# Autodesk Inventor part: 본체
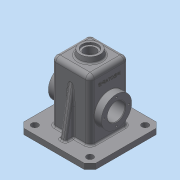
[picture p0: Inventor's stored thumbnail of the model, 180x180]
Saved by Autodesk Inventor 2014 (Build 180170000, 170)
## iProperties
Created: 2016-02
Part Number: 본체
Material: 일반
Document SubType Name: Modeling
Designer: 406-강의용
Density: 1 g/cm^3
Appearance: 기본값
Author: 406-강의용
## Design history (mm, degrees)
sketch "스케치1"
  geometry: L1 (-65, 0)-(65, 0); L2 (65, 0)-(65, 10); L3 (65, 10)-(-65, 10); L4 (-65, 10)-(-65, 0); 2 further points
  constraints: 8 end point, 2 parallel, 1 coincident, 1 horizontal, 1 midpoint, 1 perpendicular
  dimensions: "d0" = 130 distance between parallel lines of L4 L2; "d1" = 10 distance between parallel lines of L1 L3
extrude "돌출1" new body sketch "스케치1" distance "d2" = 130; taper "d3" = 0 deg
sketch "스케치2"
  geometry: L1 (130, 0)-(0, 0) reference; L2 (130, 0)-(130, -130) reference; L3 (30, -100)-(100, -100); L4 (100, -100)-(100, -30); L5 (100, -30)-(30, -30); L6 (30, -30)-(30, -100); 5 further points
  constraints: 8 end point, 4 midpoint, 2 parallel, 1 horizontal, 1 horizontal alignment, 1 perpendicular, 1 vertical alignment
  dimensions: "d4" = 70 distance between parallel lines of L3 L5; "d5" = 70 distance between parallel lines of L6 L4
extrude "돌출2" join sketch "스케치2" distance "d6" = 110; taper "d7" = 0 deg
sketch "스케치3"
  geometry: L1 (35, 35)-(95, 35); L2 (95, 35)-(95, 95); L3 (95, 95)-(35, 95); L4 (35, 95)-(35, 35); L5 (100, 100)-(30, 100) reference; L6 (100, 30)-(100, 100) reference; L7 (30, 30)-(100, 30) reference; 1 further point
  constraints: 8 end point, 2 parallel, 2 perpendicular, 1 horizontal
  dimensions: "d8" = 5 distance between parallel lines of L5 L3; "d9" = 5 distance between parallel lines of L6 L2; "d10" = 5 distance between parallel lines of L7 L1
extrude "돌출3" cut sketch "스케치3" distance "d11" = 115; taper "d12" = 0 deg
fillet "모깎기1" dims "d13" = 8
fillet "모깎기2" dims "d14" = 8
chamfer "모따기1" distance "d15" = 10; stored, may be unused: second distance "d16" = 2, angle "d17" = 45 deg
node "작업 평면1"
sketch "스케치4"
  geometry: L1 (90, 112)-(90, 10) reference; L2 (90, 10)-(120, 10) reference; L3 (120, 10)-(120, 0) reference; L4 (120, 0)-(85, 0) reference; L5 (85, 0)-(85, 115) reference; L6 (85, 115)-(25, 115) reference; L7 (25, 115)-(25, 0) reference; L8 (25, 0)-(-10, 0) reference; L9 (-10, 0)-(-10, 10) reference; L10 (-10, 10)-(20, 10) reference; L11 (20, 10)-(20, 112) reference; L12 (28, 120)-(82, 120) reference; L13 (105, 10)-(90, 95.069); A1 r 8 centre (82, 112) between (90, 112) and (82, 120) reference; A2 r 8 centre (28, 112) between (28, 120) and (20, 112) reference
  constraints: 2 end point, 1 midpoint, 1 point on line
  dimensions: "d18" = 100 deg angle of L2 L13; "d19" = 15 distance from line of L3 L13.start
extrude "돌출4" join sketch "스케치4" stored distance "d20" = 10; taper "d21" = 0 deg
fillet "모깎기3" dims "d22" = 3
fillet "모깎기4" dims "d23" = 3
node "작업 평면2"
fillet "모깎기5" dims "d24" = 3
node "작업 평면3"
sketch "스케치6"
  geometry: L1 (62, 0)-(62, -99) reference; L2 (65, -102)-(92, -102) reference; L3 (92, -102)-(92, -112) reference; L4 (92, -112)-(57, -112) reference; L5 (57, -112)-(57, 3) reference; L6 (57, 3)-(-3, 3) reference; L7 (-3, 3)-(-3, -112) reference; L8 (-3, -112)-(-38, -112) reference; L9 (-38, -112)-(-38, -102) reference; L10 (-38, -102)-(-11, -102) reference; L11 (-8, -99)-(-8, 0) reference; L12 (0, 8)-(54, 8) reference; L13 (50, -57)-(75, -57); L14 (50, -41)-(75, -41); L15 (75, -41)-(75, -29.5); L16 (75, -29.5)-(57, -29.5); L17 (57, -29.5)-(50, -36.5); L18 (50, -36.5)-(50, -41); A1 r 8 centre (54, 0) between (62, 0) and (54, 8) reference; A2 r 3 centre (65, -99) between (62, -99) and (65, -102) reference; A3 r 3 centre (-11, -99) between (-11, -102) and (-8, -99) reference; A4 r 8 centre (0, 0) between (0, 8) and (-8, 0) reference; 1 further point
  constraints: 12 end point, 3 perpendicular, 2 parallel, 2 vertical alignment, 1 point on line
  dimensions: "d30" = 55 distance between parallel lines of L4 L13; "d31" = 7 distance from line of L5 L13.start; "d32" = 25 distance of L13.start L13.end; "d33" = 32 diameter of L14 L13; "d34" = 55 diameter of L16 L13; "d35" = 135 deg angle of L5 L17
revolve "회전1" sketch "스케치6" stored, may be unused: angle "d36" = 90 deg
sketch "스케치7"
  geometry: L1 (62, 0)-(62, -29.5) reference; L2 (62, -29.5)-(75, -29.5) reference; L3 (75, -29.5)-(75, -41) reference; L4 (75, -41)-(62, -41) reference; L5 (62, -41)-(62, -73) reference; L6 (62, -73)-(75, -73) reference; L7 (75, -73)-(75, -84.5) reference; L8 (75, -84.5)-(62, -84.5) reference; L9 (62, -84.5)-(62, -99) reference; L10 (65, -102)-(92, -102) reference; L11 (92, -102)-(92, -112) reference; L12 (92, -112)-(57, -112) reference; L13 (57, -112)-(57, -84.5) reference; L14 (57, -84.5)-(50, -77.5) reference; L15 (50, -77.5)-(50, -73) reference; L16 (50, -73)-(57, -73) reference; L17 (57, -73)-(57, -41) reference; L18 (57, -41)-(50, -41) reference; L19 (50, -41)-(50, -36.5) reference; L20 (50, -36.5)-(57, -29.5) reference; L21 (57, -29.5)-(57, 3) reference; L22 (57, 3)-(-3, 3) reference; L23 (-3, 3)-(-3, -112) reference; L24 (-3, -112)-(-38, -112) reference; L25 (-38, -112)-(-38, -102) reference; L26 (-38, -102)-(-11, -102) reference; L27 (-8, -99)-(-8, 0) reference; L28 (0, 8)-(54, 8) reference; L29 (34.755, -57)-(89.812, -57); L30 (57, -57)-(62, -57); L31 (62, -57)-(62, -41); L32 (62, -41)-(57, -41); L33 (57, -41)-(57, -57); A1 r 8 centre (54, 0) between (62, 0) and (54, 8) reference; A2 r 3 centre (65, -99) between (62, -99) and (65, -102) reference; A3 r 3 centre (-11, -99) between (-11, -102) and (-8, -99) reference; A4 r 8 centre (0, 0) between (0, 8) and (-8, 0) reference; 1 further point
  constraints: 10 end point, 3 parallel, 1 horizontal, 1 midpoint, 1 perpendicular, 1 point on line
  dimensions: "d37" = 55 distance between parallel lines of L12 L29
revolve "회전2" sketch "스케치7" stored, may be unused: angle "d38" = 90 deg
fillet "모깎기8" dims "d39" = 3
fillet "모깎기9" dims "d40" = 3
chamfer "모따기2" distance "d41" = 1; stored, may be unused: second distance "d42" = 2, angle "d43" = 45 deg
fillet "모깎기10" dims "d44" = 0.5
fillet "모깎기11" dims "d45" = 0.5
sketch "스케치8"
  geometry: L1 (112, 30)-(95.332, 30) reference; L2 (94.811, 29.954)-(12.479, 15.437) reference; L3 (10, 12.483)-(10, 0) reference; L4 (10, 0)-(0, 0) reference; L5 (0, 0)-(0, 35) reference; L6 (0, 35)-(112, 35) reference; L7 (115, 38)-(115, 92) reference; L8 (112, 95)-(0, 95) reference; L9 (0, 95)-(0, 130) reference; L10 (0, 130)-(10, 130) reference; L11 (10, 130)-(10, 117.517) reference; L12 (12.479, 114.563)-(94.811, 100.046) reference; L13 (95.332, 100)-(112, 100) reference; L14 (120, 92)-(120, 38) reference; L15 (120, 65)-(130, 65); L16 (120, 45)-(130, 46.763); L17 (130, 46.763)-(130, 65); A1 r 3 centre (95.332, 27) between (95.332, 30) and (94.811, 29.954) reference; A2 r 3 centre (13, 12.483) between (12.479, 15.437) and (10, 12.483) reference; A3 r 3 centre (112, 38) between (112, 35) and (115, 38) reference; A4 r 3 centre (112, 92) between (115, 92) and (112, 95) reference; A5 r 3 centre (13, 117.517) between (10, 117.517) and (12.479, 114.563) reference; A6 r 3 centre (95.332, 103) between (94.811, 100.046) and (95.332, 100) reference; A7 r 8 centre (112, 92) between (120, 92) and (112, 100) reference; A8 r 8 centre (112, 38) between (112, 30) and (120, 38) reference
  constraints: 6 end point, 2 perpendicular, 1 midpoint, 1 parallel, 1 point on line
  dimensions: "d46" = 10 distance of L15.start L15.end; "d47" = 10 deg angle of L1 L16 (derived); "d48" = 40 diameter of L16.start L15
revolve "회전3" sketch "스케치8" stored, may be unused: angle "d49" = 90 deg
sketch "스케치9"
  geometry: C1 r 18.237 at (0, 0) reference; 1 further point
hole "구멍1" sketch "스케치9" at (0, 0) diameter "d50" = 21; stored, may be unused: countersink angle "d54" = 90 deg, drill point angle "d56" = 118 deg; dims "d51" = 6, "d52" = 28, "d53" = 4, "d55" = 8
fillet "모깎기12" dims "d57" = 3
sketch "스케치10"
  geometry: L1 (120, -10)-(120, -120) reference; L2 (110, 0)-(0, 0) reference; C1 r 6 at (105, -115); C2 r 6 at (105, -15); 1 further point
  constraints: 2 centre point, 1 vertical alignment
  dimensions: "d58" = 6 radius of C1; "d59" = 6 radius of C2; "d60" = 15 distance from line of L2 C2.centre; "d61" = 100 distance of C1.centre C2.centre; "d62" = 15 distance from line of L1 C2.centre
extrude "돌출5" cut sketch "스케치10" distance "d63" = 33; taper "d64" = 0 deg
sketch "스케치11"
  geometry: L1 (62, -99)-(62, 0) reference; L2 (8.763, 18)-(45.237, 18) reference; 2 further points
  constraints: 1 other
  dimensions: "d68" = 35 distance from line of L1 point (27, -12); "d69" = 30 distance from line of L2 point (27, -12)
feature "엠보싱1" sketch "스케치11" dims "d70" = 0.5, "d71" = 0
sketch "스케치12" dims "d72" = 22.5
  geometry: C1 r 17 at (0, 0) reference; 3 further points
  constraints: 1 coincident, 1 vertical alignment, 2 other
hole "구멍2" sketch "스케치12" at (0, 22.5) diameter "d73" = 3.242; stored, may be unused: countersink angle "d77" = 90 deg, drill point angle "d79" = 118 deg; dims "d74" = 8, "d75" = 4, "d76" = 2, "d78" = 10
node "솔리드1"
mirror "대칭1"
mirror "대칭2"
mirror "대칭3"
mirror "대칭4"
pattern_linear "직사각형 패턴1" dims "d67" = 100
pattern_circular "원형 패턴1" dims angle "d81" = 360 deg
mirror "대칭5"
node "절단 모서리 투영1"
node "절단 모서리 투영3"
node "절단 모서리 투영4"
node "절단 모서리 투영5"
